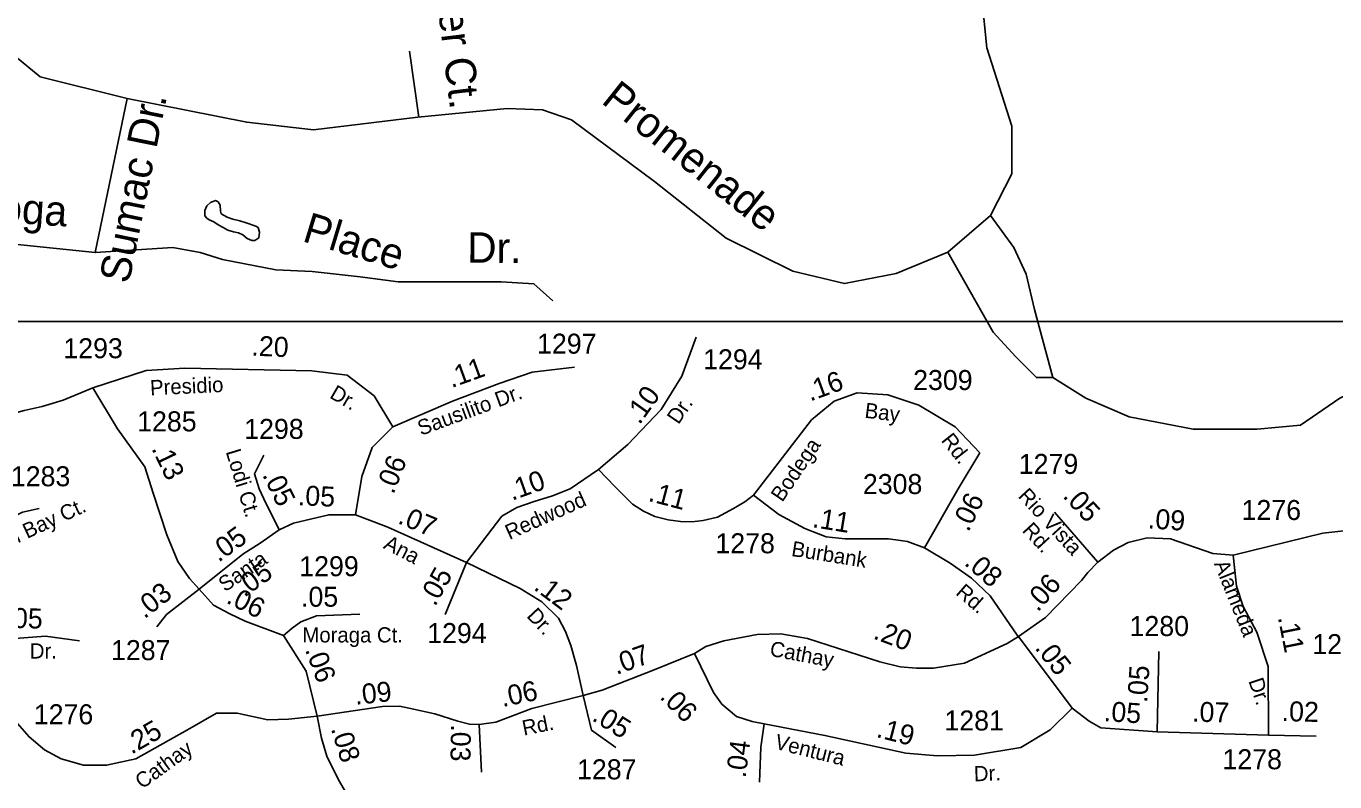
# Model space of a CAD drawing. Extents: x 2290055 to 2389491, y 66597 to 237875.
# Drawn here: x 2328416 to 2332508, y 132566 to 134927 of the extents above; entities that cross this region are included whole.
import ezdxf

# ---------------------------------------------------------------- set-up
doc = ezdxf.new("R2010")
doc.units = 0
for name, color, linetype in [('Exist Hydrographic Pond Under 1500 Sq Ft', 7, 'Continuous'), ('Exist Road Non-System Type 51', 7, 'Continuous'), ('Exist Road Non-System Type 51 Label', 7, 'Continuous'), ('Exist Road Secondary Mileage Hundredths English Label', 7, 'Continuous'), ('Exist Road Secondary Type 51 Attributed', 7, 'Continuous'), ('Exist Road Secondary Type 51 Label', 7, 'Continuous'), ('Exist Road Secondary Type 51 Number Label', 7, 'Continuous'), ('Map Preparation Inset Cut Line', 7, 'Continuous')]:
    doc.layers.add(name, color=color, linetype=linetype)

msp = doc.modelspace()

# ---------------------------------------------------------------- linework, layer by layer
at = {"layer": 'Exist Hydrographic Pond Under 1500 Sq Ft'}
msp.add_lwpolyline([(2329121.2, 134256.7), (2329107.5, 134263.4), (2329093.5, 134275.3), (2329079.7, 134281.4), (2329064, 134284.8), (2329046.5, 134289.7), (2329032.5, 134298.1), (2329016.2, 134305.8), (2329002.5, 134315.3), (2328988, 134322.2), (2328981, 134326.5), (2328974.5, 134334.2), (2328974.2, 134351.3), (2328980.5, 134365.2), (2328992, 134375.7), (2329007.7, 134381.9), (2329016, 134378.3), (2329022.5, 134367.8), (2329024, 134348.4), (2329026.2, 134340.7), (2329044.5, 134330.1), (2329062.5, 134323.6), (2329083.7, 134318.6), (2329103.5, 134312.7), (2329134.2, 134302.2), (2329141, 134297.7), (2329146, 134283.1), (2329143.5, 134265.3), (2329131.2, 134257.5), (2329121.2, 134256.7)], dxfattribs=at)
at = {"layer": 'Exist Road Non-System Type 51'}
for points in [[(2331399.6, 135055.7), (2331419.3, 134858.8), (2331498, 134614.7), (2331498, 134465.1), (2331431.1, 134335.1), (2331297.3, 134220.9), (2331136, 134154), (2330974.6, 134122.5), (2330813.3, 134161.8), (2330604.7, 134264.2), (2330380.4, 134441.4), (2330120.7, 134634.4), (2330030.2, 134665.9), (2329920.1, 134669.8), (2329640.7, 134642.3), (2329314.1, 134602.9), (2329105.5, 134626.5), (2328731.7, 134701.3), (2328460.2, 134768.3), (2328310.6, 134890.3), (2328145.4, 135355)], [(2329614.4, 134848.9), (2329643.9, 134642.6)], [(2328731.7, 134701.3), (2328632.3, 134219.2), (2328379.5, 134246.1), (2328202, 134246.1), (2328083.7, 134203.1), (2327997.7, 134127.7)], [(2331431.1, 134335.1), (2331503.6, 134235.8), (2331542.3, 134151.9), (2331568.1, 134042.1), (2331626.2, 133828.9)], [(2328632.3, 134219.2), (2328874.3, 134235.4), (2328960.4, 134219.2), (2329030.3, 134197.7), (2329197, 134165.4), (2329310, 134160), (2329460.6, 134143.9), (2329578.9, 134127.7), (2329745.6, 134127.7), (2329901.6, 134127.7), (2330003.8, 134122.3), (2330063, 134068.5)], [(2331297.3, 134220.9), (2331439, 133971), (2331510, 133893.5), (2331574.6, 133828.9), (2331626.2, 133828.9), (2331729.5, 133764.3), (2331865, 133706.2), (2332065.1, 133667.5), (2332265.2, 133667.5), (2332400.7, 133680.4), (2332523.4, 133764.3), (2332646, 133822.5), (2332813.2, 133846.4)]]:
    msp.add_lwpolyline(points, dxfattribs=at)
at = {"layer": 'Exist Road Secondary Type 51 Attributed'}
for points in [[(2330510.9, 133955.5), (2330465.7, 133832.8), (2330401.2, 133729.5), (2330296.8, 133620.1), (2330205.3, 133542.1)], [(2328624.4, 133797.1), (2328791.1, 133850.6), (2328912.5, 133857.9), (2329309.2, 133849.7), (2329420.1, 133836), (2329504, 133771.4), (2329562.1, 133674.6)], [(2329562.1, 133674.6), (2329749.3, 133755.3), (2329894.5, 133810.2), (2329997.8, 133845.7), (2330130.1, 133861.9)], [(2328014.7, 133658.3), (2328070.6, 133673.4), (2328136.9, 133688.6), (2328206.7, 133697.2), (2328314.1, 133703.8), (2328368.6, 133714.2), (2328410.3, 133725.6), (2328466.2, 133738.9), (2328531.6, 133758.8), (2328624.4, 133797.1)], [(2328624.4, 133797.1), (2328701.2, 133668.7), (2328786.6, 133550), (2328812.7, 133467.7), (2328856.1, 133337.2), (2328890.6, 133254.2), (2328926.8, 133201.6), (2328956.8, 133167.5)], [(2330690, 133461.9), (2330871.7, 133697.2), (2330942.7, 133755.3), (2331013.7, 133781.1), (2331110.5, 133774.7), (2331207.3, 133742.4), (2331320.3, 133674.6), (2331397.7, 133593.8)], [(2329445.9, 133400.1), (2329465.3, 133519.5), (2329497.5, 133610), (2329562.1, 133674.6)], [(2329207.2, 133353), (2329158.8, 133450.1), (2329144.9, 133481.5), (2329129.8, 133528), (2329158.8, 133586.3)], [(2331225.1, 133296.5), (2331330, 133480.8), (2331397.7, 133593.8)], [(2330205.3, 133542.1), (2330117.2, 133481.1), (2330061.2, 133459.1), (2330003.9, 133441.7), (2329950.2, 133422.7), (2329903.6, 133396), (2329793.1, 133250.6)], [(2330205.3, 133542.1), (2330256.3, 133488.1), (2330311.8, 133433.5), (2330345.8, 133411.5), (2330381.8, 133395.2), (2330423.4, 133384.9), (2330461.8, 133378.9), (2330497.3, 133377.9), (2330532.3, 133382.5), (2330577.5, 133392.3), (2330627.1, 133419.4), (2330662.8, 133440.4), (2330690, 133461.9)], [(2331225.1, 133296.5), (2331171.6, 133316.9), (2331141.9, 133321.1), (2331111.8, 133325.5), (2330976.5, 133325.5), (2330917.3, 133331.7), (2330851, 133357.4), (2330768.9, 133401), (2330690, 133461.9)], [(2328172.7, 133293.8), (2328404.4, 133408.5), (2328457.2, 133420.3)], [(2329207.2, 133353), (2329252.3, 133374.2), (2329362, 133400.1), (2329445.9, 133400.1)], [(2329445.9, 133400.1), (2329546.6, 133361.3), (2329793.1, 133250.6)], [(2331766.2, 133252.6), (2331631.4, 133408.4)], [(2328956.8, 133167.5), (2329093.4, 133276.8), (2329147.4, 133311.8), (2329207.2, 133353)], [(2332864, 133365.4), (2332582.8, 133354.8), (2332469.7, 133342.6), (2332190, 133273.6)], [(2332190, 133273.6), (2332126.2, 133279.7), (2331993.8, 133324.9), (2331921, 133328.1), (2331861.1, 133313.6), (2331815.9, 133289.2), (2331766.2, 133252.6)], [(2331520.5, 133016.1), (2331514.8, 133024.1), (2331430.4, 133146.9), (2331371.4, 133202.6), (2331305.1, 133249.4), (2331225.1, 133296.5)], [(2332190, 133273.6), (2332200.2, 133177.5), (2332220.9, 133114.1), (2332263.6, 133033.8), (2332299.4, 132925.8), (2332299.9, 132711.4)], [(2329793.1, 133250.6), (2329725.6, 133088.9)], [(2329793.1, 133250.6), (2329960.3, 133170.2), (2330027.9, 133128.2), (2330080, 133077), (2330101.8, 133035.2), (2330119.2, 132991.4), (2330136.5, 132929.2), (2330157.5, 132836)], [(2331766.2, 133252.6), (2331735.7, 133220.2), (2331715.4, 133194.6), (2331602.8, 133079.1), (2331518.1, 133019.4)], [(2328824.9, 133049.8), (2328855.2, 133088.3), (2328956.8, 133167.5)], [(2328956.8, 133167.5), (2329002.1, 133118.2), (2329052.9, 133091), (2329100.9, 133067.4), (2329220.5, 133022.5)], [(2329220.5, 133022.5), (2329247.4, 133045.9), (2329274.8, 133065.6), (2329323.7, 133084.6), (2329458.8, 133090)], [(2328285.9, 132985.9), (2328350.4, 133007.7), (2328394.8, 133014.4), (2328476.9, 133021.1), (2328582.5, 133006)], [(2329220.5, 133022.5), (2329291.1, 132911.3), (2329325.8, 132770.5)], [(2331518.1, 133019.4), (2331482.9, 132997.9), (2331350, 132936.4), (2331252.4, 132921), (2331199.5, 132921), (2331148.2, 132925.3), (2331085.2, 132941.1), (2330858.9, 133013.5), (2330775.3, 133028.1), (2330702, 133025.9), (2330597.7, 133006.7), (2330541, 132989), (2330506, 132967.1)], [(2331685.9, 132795.8), (2331518.1, 133019.4)], [(2329325.8, 132770.5), (2329236.3, 132761.4), (2329171.4, 132759.6), (2329075.4, 132780), (2329010.9, 132780), (2328920.5, 132728.3), (2328759.1, 132637.9), (2328667.5, 132617.6), (2328595.4, 132617.6), (2328525.1, 132637.7), (2328473.1, 132666.2), (2328425, 132706.2), (2328388.9, 132748.2), (2328365.5, 132785), (2328337, 132850.5), (2328285.9, 132985.9)], [(2331951.7, 132721.9), (2331957.3, 132973.2)], [(2330506, 132967.1), (2330379.2, 132915.6), (2330216.8, 132851.9), (2330157.5, 132836)], [(2330723.7, 132746.8), (2330685.6, 132753.8), (2330637.1, 132770.4), (2330591.4, 132808.2), (2330564.7, 132844.5), (2330506, 132967.1)], [(2330157.5, 132836), (2329996.7, 132795.2), (2329884.3, 132752.3), (2329832.3, 132745)], [(2330157.5, 132836), (2330183.9, 132726.7), (2330259.7, 132672.7)], [(2329832.3, 132745), (2329802.2, 132745.9), (2329765.6, 132755), (2329693.5, 132777.9), (2329617.7, 132795.2), (2329583, 132802.5), (2329530, 132801.6), (2329325.8, 132770.5)], [(2329325.8, 132770.5), (2329339, 132701.8), (2329355.9, 132645.6), (2329392.4, 132572.5), (2329417.2, 132529.1)], [(2331685.9, 132795.8), (2331617.2, 132728.3), (2331525.6, 132672.6), (2331380.8, 132648.7), (2331264.9, 132647.4), (2331166.7, 132655), (2330913.3, 132710.8), (2330723.7, 132746.8)], [(2331951.7, 132721.9), (2331776, 132734.2), (2331739.7, 132755.4), (2331685.9, 132795.8)], [(2329832.3, 132745), (2329840.1, 132596.1)], [(2330723.7, 132746.8), (2330713, 132674.4), (2330708.7, 132564.3)], [(2332299.9, 132711.4), (2331951.7, 132721.9)], [(2332449.7, 132708.7), (2332299.9, 132711.4)]]:
    msp.add_lwpolyline(points, dxfattribs=at)
at = {"layer": 'Map Preparation Inset Cut Line'}
for points in [[(2326073, 125795.4), (2326049.1, 134004.6), (2335243.2, 134004.6), (2335243.2, 141886.2), (2343900.4, 141886.2), (2341393.8, 134004.6), (2339225, 125795.4)], [(2341393.8, 134004.6), (2335243.2, 134004.6), (2326049.1, 134004.6), (2326073, 125795.4), (2339225, 125795.4)]]:
    msp.add_lwpolyline(points, close=True, dxfattribs=at)

# ---------------------------------------------------------------- texts
at = {"layer": 'Exist Road Non-System Type 51 Label'}
for s, rotation, p in [('Tower Ct.', 276.9291, (2329675.6, 135210.4)), ('Promenade', 321.4809, (2330211, 134688.8)), ('Sumac Dr.', 78.5185, (2328737.3, 134119.6)), ('Chattooga', 356.4996, (2327956.7, 134336.7)), ('Place', 343.0667, (2329276.2, 134255.8)), ('Dr.', 359.4122, (2329794.6, 134188.2))]:
    msp.add_text(s, height=95, rotation=rotation, dxfattribs=at).set_placement(p)
at = {"layer": 'Exist Road Secondary Mileage Hundredths English Label'}
for s, rotation, p in [('.20', 357.6124, (2329119.4, 133897.5)), ('.11', 19.8697, (2329746.1, 133795.7)), ('.16', 19.9959, (2330867.3, 133753.8)), ('.10', 54.4839, (2330333.7, 133679.4)), ('.13', 295.6497, (2328807.1, 133607.2)), ('.06', 68.2133, (2329564.1, 133461.8)), ('.05', 296.0787, (2329153.4, 133525)), ('.10', 19.6687, (2329934.9, 133443.8)), ('.05', 357.4347, (2329264.5, 133430.2)), ('.11', 345.245, (2330358.3, 133444.2)), ('.06', 64.0587, (2331361.9, 133344.3)), ('.05', 312.9671, (2331654.5, 133456.7)), ('.07', 337.4257, (2329575, 133374.6)), ('.11', 350.9027, (2330871.8, 133361.8)), ('.09', 356.0694, (2331921.5, 133358)), ('.05', 35.9632, (2329017.7, 133250)), ('.08', 318.969, (2331346.1, 133245.8)), ('.05', 35.9632, (2329098.1, 133140.3)), ('.05', 60.7272, (2329694.3, 133111.4)), ('.06', 48.526, (2331578.6, 133094.2)), ('.03', 38.1789, (2328786, 133073.3)), ('.12', 323.1087, (2330000, 133168.6)), ('.06', 333.4172, (2329038.3, 133126.3)), ('.05', 358.4062, (2328350.9, 133047.6)), ('.20', 339.4291, (2331061.5, 133014.3)), ('.11', 281.3013, (2332329.1, 133079.5)), ('.06', 290.7573, (2329287.2, 132978.7)), ('.07', 19.668, (2330261.5, 132899.7)), ('.05', 308.272, (2331567.5, 132983.5)), ('.05', 86.0583, (2331920.5, 132811.8)), ('.09', 6.0565, (2329445.9, 132806.2)), ('.06', 11.4224, (2329905.5, 132799.3)), ('.06', 314.9775, (2330394.2, 132828.7)), ('.05', 356.36, (2331784.1, 132755.7)), ('.07', 358.4402, (2332060.6, 132754)), ('.02', 358.4399, (2332340.6, 132755.8)), ('.05', 327.9739, (2330182.1, 132759.5)), ('.25', 29.7643, (2328745.3, 132650.3)), ('.08', 287.1508, (2329368.3, 132731.9)), ('.03', 269.2439, (2329744.2, 132745.9)), ('.19', 345.7531, (2331071.3, 132706.2)), ('.04', 82.5325, (2330665.2, 132576.3))]:
    msp.add_text(s, height=62.5, rotation=rotation, dxfattribs=at).set_placement(p)
msp.add_text('.05', height=62.5, dxfattribs=at).set_placement((2329275.5, 133112.9))
at = {"layer": 'Exist Road Secondary Type 51 Label'}
for s, rotation, p in [('Presidio', 2.6397, (2328804.4, 133773.4)), ('Dr.', 329.7236, (2329361.9, 133767.3)), ('Sausilito Dr.', 20.1508, (2329650.2, 133646.8)), ('Dr.', 55.6403, (2330455.2, 133680.1)), ('Bay', 352.8687, (2331035.8, 133703.7)), ('Bodega', 55.9432, (2330780.1, 133437.5)), ('Rd.', 308.1347, (2331274.6, 133632)), ('Lodi Ct.', 286.9297, (2329039.6, 133597.6)), ('Redwood', 24.1293, (2329926.9, 133321.1)), ('Rio Vista', 312.6869, (2331514.6, 133456.7)), ('Suisun Bay Ct.', 24.8293, (2328226.8, 133235.6)), ('Rd.', 312.6869, (2331527.7, 133349.5)), ('Ana', 332.419, (2329530.1, 133296.8)), ('Burbank', 350.9027, (2330806.4, 133271.7)), ('Santa', 34.4014, (2329037.8, 133157.5)), ('Alameda', 291.9291, (2332129.1, 133247.4)), ('Rd.', 318.969, (2331319.5, 133152.9)), ('Dr.', 313.1297, (2329978.5, 133082.2)), ('Cathay', 349.3725, (2330738.4, 132959.9)), ('Dr.', 288.5651, (2332236.9, 132881.4)), ('Rd.', 11.4224, (2329972, 132709.9)), ('Cathay', 35.8587, (2328778.4, 132541.5)), ('Ventura', 345.9536, (2330753.5, 132669.7)), ('Dr.', 2.2046, (2331379.8, 132567.1))]:
    msp.add_text(s, height=47.5, rotation=rotation, dxfattribs=at).set_placement(p)
for s, p in [('Moraga Ct.', (2329279.8, 133001.2)), ('Dr.', (2328427.5, 132951.1))]:
    msp.add_text(s, height=47.5, dxfattribs=at).set_placement(p)
at = {"layer": 'Exist Road Secondary Type 51 Number Label'}
for s, p in [('1297', (2330013.4, 133903.6)), ('1293', (2328532.4, 133889.3)), ('1294', (2330532.6, 133854.8)), ('2309', (2331189.2, 133790)), ('1285', (2328763.1, 133660.8)), ('1298', (2329097.8, 133637.3)), ('1279', (2331519.4, 133527.8)), ('1283', (2328368.2, 133489.3)), ('2308 ', (2331032, 133465)), ('1276', (2332216, 133383.9)), ('1278', (2330571, 133279.9)), ('1299', (2329269.9, 133208.2)), ('1294', (2329669.9, 132999.4)), ('1280', (2331865.8, 133021.3)), ('1277', (2332437.1, 132964.8)), ('1287', (2328681.4, 132946.1)), ('1276', (2328439.9, 132745.6)), ('1281', (2331287, 132726.2)), ('1278', (2332156.2, 132605.1)), ('1287', (2330138.3, 132573.6))]:
    msp.add_text(s, height=62.5, dxfattribs=at).set_placement(p)

doc.saveas('drawing.dxf')
